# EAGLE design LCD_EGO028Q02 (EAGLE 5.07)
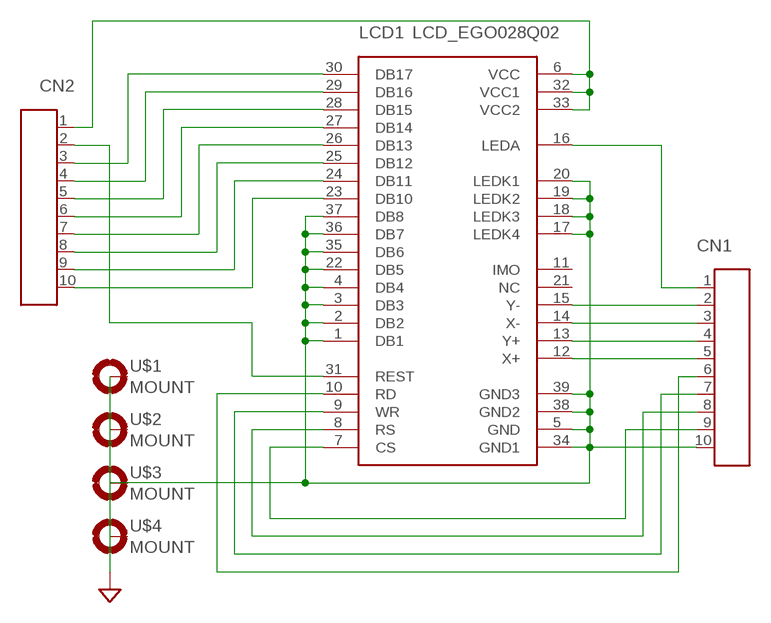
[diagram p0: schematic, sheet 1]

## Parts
CN1  CON_10P  [CON_HRS_DIP_10]
CN2  CON_10P  [CON_HRS_DIP_10]
LCD1  LCD_EGO028Q02  [LCD_EGO028Q02]
U$1  MOUNT  MOUNT-PAD2.1  [PAD-2.1]
U$2  MOUNT  MOUNT-PAD2.1  [PAD-2.1]
U$3  MOUNT  MOUNT-PAD2.1  [PAD-2.1]
U$4  MOUNT  MOUNT-PAD2.1  [PAD-2.1]

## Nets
GND: CN1.10 LCD1.1(DB1) LCD1.2(DB2) LCD1.3(DB3) LCD1.4(DB4) LCD1.5(GND) LCD1.17(LEDK4) LCD1.18(LEDK3) LCD1.19(LEDK2) LCD1.20(LEDK1) LCD1.22(DB5) LCD1.34(GND1) LCD1.35(DB6) LCD1.36(DB7) LCD1.37(DB8) LCD1.38(GND2) LCD1.39(GND3) U$1.B2,1(MOUNT) U$2.B2,1(MOUNT) U$3.B2,1(MOUNT) U$4.B2,1(MOUNT)
N$1: CN2.3 LCD1.30(DB17)
N$2: CN2.4 LCD1.29(DB16)
N$3: CN2.5 LCD1.28(DB15)
N$4: CN2.6 LCD1.27(DB14)
N$5: CN2.7 LCD1.26(DB13)
N$6: CN2.8 LCD1.25(DB12)
N$7: CN2.9 LCD1.24(DB11)
N$8: CN2.10 LCD1.23(DB10)
N$9: CN2.2 LCD1.31(REST)
N$10: CN1.6 LCD1.10(RD)
N$11: CN1.7 LCD1.9(WR)
N$12: CN1.8 LCD1.8(RS)
N$13: CN1.9 LCD1.7(CS)
N$14: CN1.2 LCD1.15(Y-)
N$15: CN1.3 LCD1.14(X-)
N$16: CN1.4 LCD1.13(Y+)
N$17: CN1.5 LCD1.12(X+)
N$19: CN2.1 LCD1.6(VCC) LCD1.32(VCC1) LCD1.33(VCC2)
N$20: CN1.1 LCD1.16(LEDA)
Unconnected: LCD1.11(IMO) LCD1.21(NC)

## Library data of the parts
CN1 CN2 = MyLib:CON_10P: 10P Molex Connector
LCD1 = MyLib:LCD_EGO028Q02: 2.8" Color LCD 240x320dot with Touch Screen
U$1-U$4 = MyLib:MOUNT-PAD: 2.1mm Mount Pad (Connectable to GND)

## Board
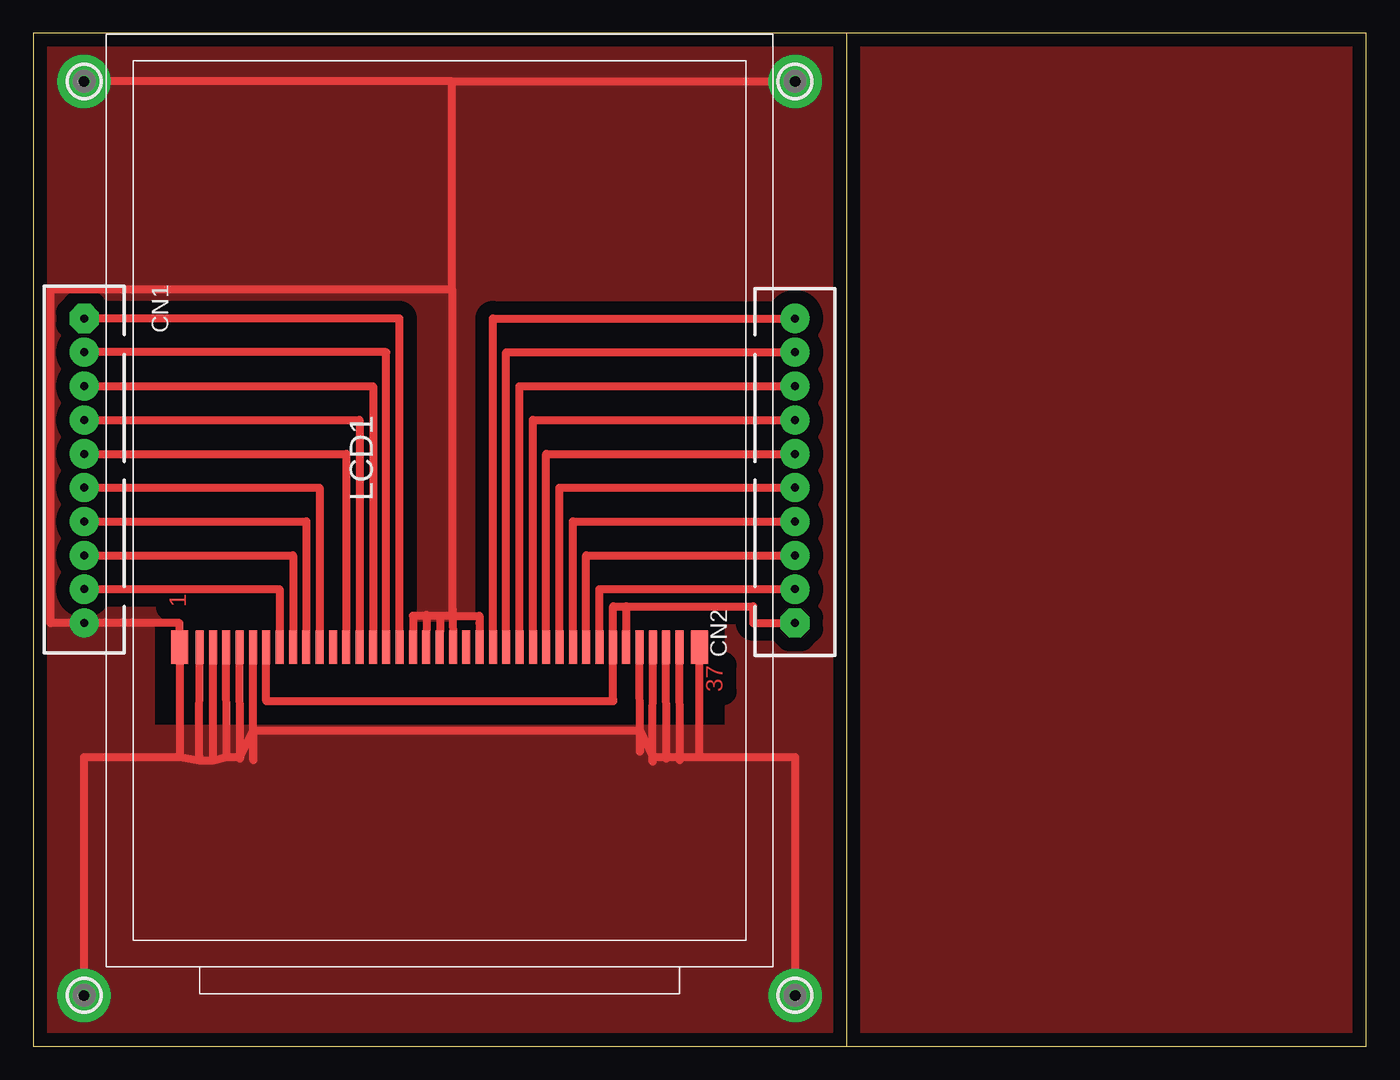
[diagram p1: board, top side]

Size 100 x 76 mm. Coordinates in mm from the lower left corner, seen from the top.
Outline: 61,0 0,0 0,76 61,76
Outline: 61,0 100,0 100,76 61,76
Outline: 61,76 61,0
Copper layers (1*16): Top 0.035mm / dielectric 1.5mm / Bottom 0.035mm
Design rules "default": minimum track width 10mil, minimum drill 24mil, track to track 8mil, track to pad 8mil, pad to pad 8mil, via to via 8mil, smd to smd 8mil, copper to edge 40mil, drill to drill 8mil, minimum pad ring 10mil, minimum via ring 8mil, stop-mask expansion 4mil, vias tented up to drill 0mil, thermal gap 10mil

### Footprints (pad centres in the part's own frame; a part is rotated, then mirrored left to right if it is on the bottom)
CON_HRS_DIP_10 = drill 0.6 pad 2.184 octagon: 1 -11.43,0 | drill 0.6 pad 2.184 round: 2 -8.89,0; 3 -6.35,0; 4 -3.81,0; 5 -1.27,0; 6 1.27,0; 7 3.81,0; 8 6.35,0; 9 8.89,0; 10 11.43,0
LCD_EGO028Q02 = smd 2.5 x 0.6: 1 0,18; 2 0,17; 3 0,16; 4 0,15; 5 0,14; 6 0,13; 7 0,12; 8 0,11; 9 0,10; 10 0,9; 11 0,8; 12 0,7; 13 0,6; 14 0,5; 15 0,4; 16 0,3; 17 0,2; 18 0,1; 19 0,0; 20 0,-1; 21 0,-2; 22 0,-3; 23 0,-4; 24 0,-5; 25 0,-6; 26 0,-7; 27 0,-8; 28 0,-9; 29 0,-10; 30 0,-11; 31 0,-12; 32 0,-13; 33 0,-14; 34 0,-15; 35 0,-16; 36 0,-17; 37 0,-18 | smd 2.54 x 1.27: 38 0,19.5; 39 0,-19.5
PAD-2.1 = drill 0.8 pad 4 round: B2,1 0,0

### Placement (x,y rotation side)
CN1  3.81,43.18 270 top
CN2  57.15,43.18 90 top
LCD1  30.48,29.94 90 top
U$1  3.81,72.39 0 top
U$2  57.15,72.39 0 top
U$3  57.15,3.81 0 top
U$4  3.81,3.81 0 top

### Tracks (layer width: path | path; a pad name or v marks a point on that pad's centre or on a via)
GND
  Top 0.61: 11,21.7 11,27.94 LCD1.38 10.98,31.75 CN1.10 1.3,31.75 1.3,56.8 31.4,56.8 | 11,21.7 12.45,21.45 | 12.45,21.45 13.5,21.45 | 13.5,21.45 14.5,21.7 | 14.5,21.7 15.5,21.7 | 15.5,21.7 16.5,23.7 | 16.5,23.7 45.5,23.7 | 45.5,23.7 46.47,21.7 | 46.47,21.7 47.5,21.7 | 47.5,21.7 48.5,21.7 | 48.5,21.7 49.98,21.7 | 49.98,21.7 LCD1.39 | LCD1.1 12.45,21.72 12.45,21.45 | LCD1.2 13.5,21.59 13.5,21.45 | LCD1.3 14.5,21.84 14.5,21.7 | LCD1.4 15.5,21.59 15.5,21.7 | LCD1.5 16.5,21.46 16.5,23.7 | LCD1.37 48.5,21.46 48.5,21.7 | LCD1.36 47.5,21.59 47.5,21.7 | LCD1.35 46.47,21.34 46.47,21.7 | LCD1.34 45.5,22.1 45.5,23.7 | LCD1.22 33.47,31.75 33.47,32.3 31.47,32.3 | 29.5,32.3 28.48,32.3 LCD1.17 | 30.5,32.3 29.5,32.3 | 31.4,32.3 30.5,32.3 | 31.4,32.3 31.47,32.3 | LCD1.20 31.47,32.77 31.47,32.3 | LCD1.19 30.5,32.13 30.5,32.3 | LCD1.18 29.5,32.38 29.5,32.3 | 31.4,56.8 31.4,32.3 | 49.98,21.7 57.15,21.7 U$3.B2,1 | 11,21.7 3.81,21.7 U$4.B2,1 | 31.4,72.39 U$2.B2,1 | 31.4,56.8 31.4,72.39 | 31.4,72.39 U$1.B2,1
  pour Top (isolate 1.016, no thermals): 0,76 61,76 61,21 52,21 52,32 9,32 9,21 0,21
  pour Top (isolate 1.016, no thermals): 0,24 61,24 61,-1 0,-1
N$1
  Top 0.61: CN2.3 41.48,36.83 LCD1.30
N$2
  Top 0.61: CN2.4 40.48,39.37 LCD1.29
N$3
  Top 0.61: CN2.5 39.48,41.91 LCD1.28
N$4
  Top 0.61: CN2.6 38.48,44.45 LCD1.27
N$5
  Top 0.61: CN2.7 37.48,46.99 LCD1.26
N$6
  Top 0.61: CN2.8 36.48,49.53 LCD1.25
N$7
  Top 0.61: CN2.9 35.48,52.07 LCD1.24
N$8
  Top 0.61: CN2.10 34.48,54.61 LCD1.23
N$9
  Top 0.61: CN2.2 42.48,34.29 LCD1.31
N$10
  Top 0.61: CN1.6 21.48,41.91 LCD1.10
N$11
  Top 0.61: CN1.7 20.48,39.37 LCD1.9
N$12
  Top 0.61: CN1.8 19.48,36.83 LCD1.8
N$13
  Top 0.61: CN1.9 18.48,34.29 LCD1.7
N$14
  Top 0.61: CN1.2 26.48,52.07 LCD1.15
N$15
  Top 0.61: CN1.3 25.48,49.53 LCD1.14
N$16
  Top 0.61: CN1.4 24.48,46.99 LCD1.13
N$17
  Top 0.61: CN1.5 23.48,44.45 LCD1.12
N$18
  pour Top (isolate 1.016): 61,76 100,76 100,0 61,0
N$19
  Top 0.61: 44.48,33 54,33 54,31.75 CN2.1 | 44.48,33 LCD1.33 | 44.48,33 43.51,32.99 43.48,32.92 43.48,31.75 LCD1.32 43.5,26 43.5,25.9 17.48,25.9 LCD1.6
N$20
  Top 0.61: CN1.1 27.48,54.61 LCD1.16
